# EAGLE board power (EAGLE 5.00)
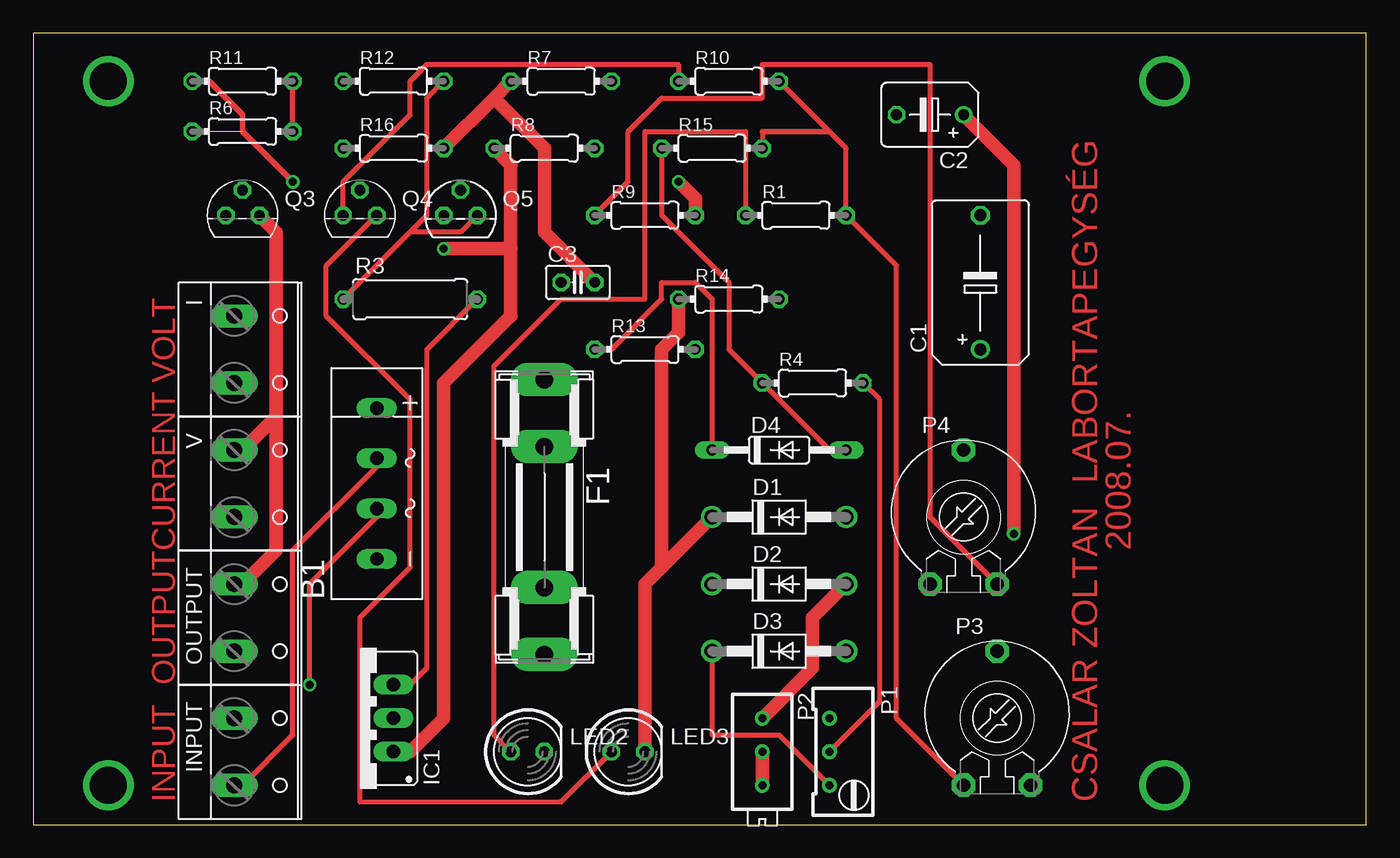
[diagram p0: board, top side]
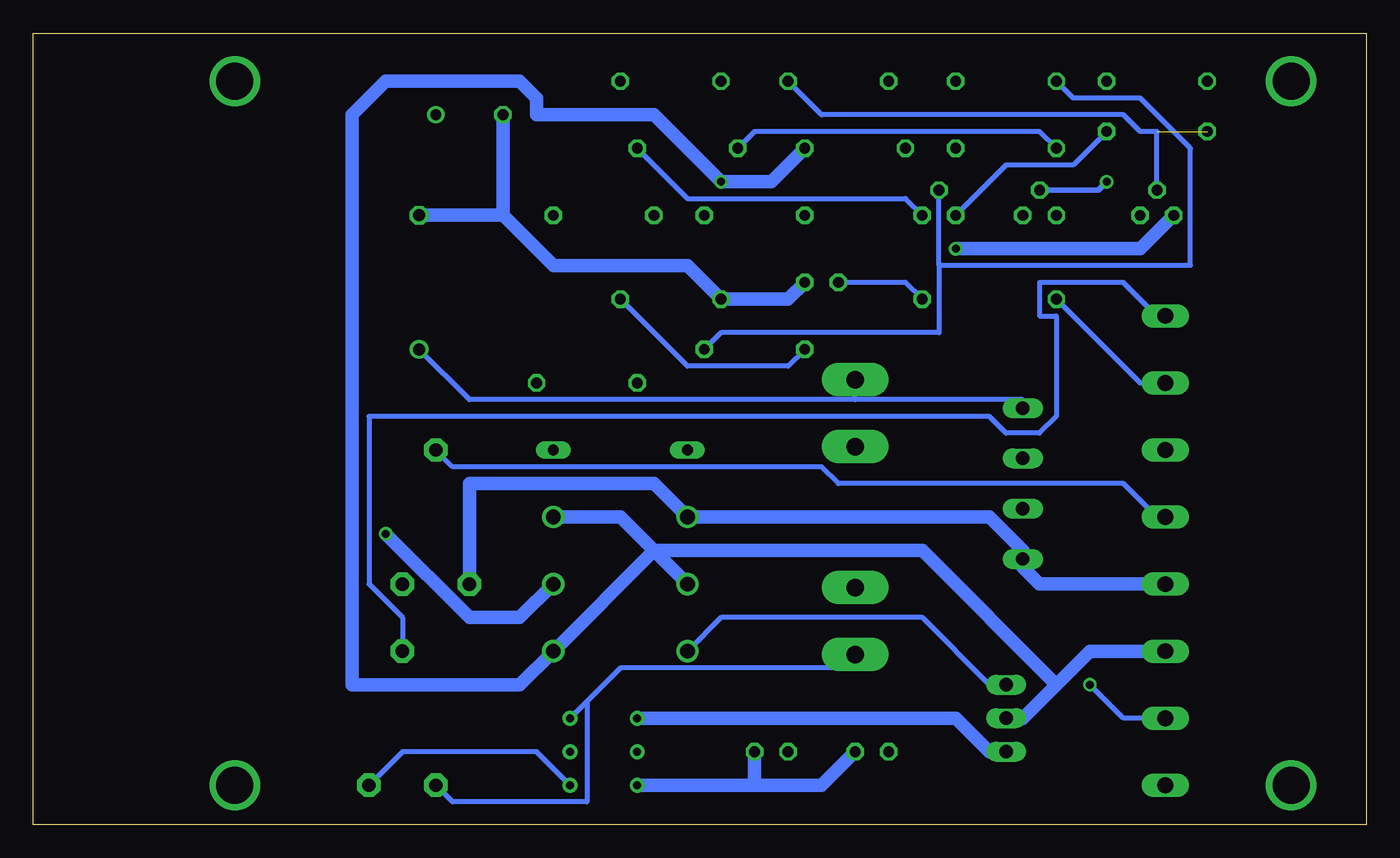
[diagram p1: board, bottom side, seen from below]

Size 101 x 60 mm. Coordinates in mm from the lower left corner, seen from the top.
Outline: 0,0 101,0 101,60 0,60 0,0
Copper layers (1*16): Top 0.035mm / dielectric 1.5mm / Bottom 0.035mm
Design rules "default": minimum track width 10mil, minimum drill 24mil, track to track 8mil, track to pad 8mil, pad to pad 8mil, via to via 8mil, smd to smd 8mil, copper to edge 40mil, drill to drill 8mil, minimum pad ring 10mil, minimum via ring 8mil, stop-mask expansion 4mil, vias tented up to drill 0mil, thermal gap 10mil
Net classes: 0 default: width 0.381 mm; 1 1: width 1.016 mm, drill 0.584 mm, clearance 0.381 mm

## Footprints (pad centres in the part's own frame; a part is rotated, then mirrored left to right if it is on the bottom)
2KBP = drill 1.016 long: + 5.715,0; - -5.715,0; AC1 -1.905,0; AC2 1.905,0
B45181C = drill 0.914 round: + -5.08,0 | drill 0.914 octagon: - 5.08,0
B45181B = drill 0.813 round: + -2.54,0 | drill 0.813 octagon: - 2.54,0
C025-025X050 = drill 0.813 octagon: 1 -1.27,0; 2 1.27,0
DO41-10 = drill 1.118 round: A 5.08,0; C -5.08,0
DO35-10 = drill 0.813 long: A 5.08,0; C -5.08,0
SHK20L = drill 1.321 pad 2.54 long: 1A -10.414,0; 1B -5.334,0; 2A 10.414,0; 2B 5.334,0
W237-132 = drill 1.194 long: 1 -2.54,-0.635; 2 2.54,-0.635
317TS = drill 1.016 long: 1 -2.54,-2.54; 2 0,-2.54; 3 2.54,-2.54
LED5MM = drill 0.813 octagon: A -1.27,0; K 1.27,0
RTRIM64W = drill 0.61 round: 1 1.27,-2.54; 2 1.27,0; 3 1.27,2.54
RTRIM3296X = drill 0.61 round: 1 0,-2.54; 2 0,0; 3 0,2.54
PT-10 = drill 1.016 pad 1.778 octagon: 1 -2.54,-5.08; 2 2.54,-5.08; 3 0,5.08
TO92 = drill 0.813 octagon: 1 1.27,0; 2 0,1.905; 3 -1.27,0
0204/7 = drill 0.813 octagon: 1 -3.81,0; 2 3.81,0
0309/10 = drill 0.813 octagon: 1 -5.08,0; 2 5.08,0

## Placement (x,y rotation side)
B1  [2KBP]  26.03,25.87 90 top
C1  2200  [B45181C]  71.75,41.11 90 top
C2  [B45181B]  67.94,53.81 180 top
C3  [C025-025X050]  41.27,41.11 0 top
D1  1N4004  [DO41-10]  56.51,23.33 0 top
D2  1N4004  [DO41-10]  56.51,18.25 0 top
D3  1N4004  [DO41-10]  56.51,13.17 0 top
D4  1N4148  [DO35-10]  56.51,28.41 0 top
F1  FUSESHK20L  [SHK20L]  38.73,23.33 270 top
I  [W237-132]  15.87,36.03 270 top
IC1  [317TS]  24.76,8.09 90 top
INPUT  [W237-132]  15.87,5.55 270 top
LED2  [LED5MM]  37.46,5.55 0 top
LED3  [LED5MM]  45.08,5.55 0 top
OUTPUT  [W237-132]  15.87,15.71 270 top
P1  [RTRIM64W]  61.59,5.55 180 top
P2  [RTRIM3296X]  55.24,5.55 180 top
P3  1  [PT-10]  73.02,8.09 0 top
P4  [PT-10]  70.48,23.33 0 top
Q3  BC237  [TO92]  15.87,46.19 0 top
Q4  BC237  [TO92]  24.76,46.19 0 top
Q5  BC327  [TO92]  32.38,46.19 0 top
R1  2.7  [0204/7]  57.78,46.19 0 top
R3  2.2  [0309/10]  28.57,39.84 0 top
R4  [0204/7]  59.05,33.49 0 top
R6  [0204/7]  15.87,52.54 0 top
R7  [0204/7]  40,56.35 0 top
R8  [0204/7]  38.73,51.27 0 top
R9  [0204/7]  46.35,46.19 0 top
R10  [0204/7]  52.7,56.35 0 top
R11  [0204/7]  15.87,56.35 0 top
R12  [0204/7]  27.3,56.35 0 top
R13  [0204/7]  46.35,36.03 0 top
R14  [0204/7]  52.7,39.84 0 top
R15  [0204/7]  51.43,51.27 0 top
R16  [0204/7]  27.3,51.27 0 top
V  [W237-132]  15.87,25.87 270 top

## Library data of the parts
B1 = rectifier
C1-C3 P1-P4 R1 R3 R4 R6-R16 = rcl
D1-D4 = diode
F1 = fuse
I INPUT OUTPUT V = con-wago-508
IC1 = v-reg
LED2 LED3 = led
Q3 Q4 = transistor-npn
Q5 = transistor-pnp

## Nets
INPUT: B1.AC2 INPUT.2
N$1: LED2.A R1.1
N$4: B1.+ C1.+ F1.1A
N$7: Q3.2 R6.1 R7.2
N$9: LED3.A Q4.1
N$10: C3.1 D3.C IC1.3 P1.3 P3.2 R3.2
N$11: P1.2 R4.2
N$12: Q4.3 R10.1
N$13: Q4.2 R11.1
N$14: Q5.3 R6.2 R11.2
N$15: P4.2 R9.1
N$16 [1]: C2.+ D2.A IC1.1 P2.1 Q3.3 R8.1
N$17: D4.C R13.1 R14.2
N$18: Q5.2 R12.1 R13.2
N$19 [1]: D1.A D2.C D3.A IC1.2 OUTPUT.2 R8.2 R9.2
N$20: I.1 P3.3
N$22: P4.3 V.2
N$23: F1.2A I.2 P1.1 P3.1 Q5.1 R1.2 R3.1 R10.2 R12.2 R15.2
N$24 [1]: B1.- C1.- C2.- C3.2 D1.C LED2.K LED3.K OUTPUT.1 P2.2 P2.3 P4.1 Q3.1 R7.1 R14.1 R16.2 V.1
N$25: D4.A R4.1 R15.1 R16.1
N$31: B1.AC1 INPUT.1

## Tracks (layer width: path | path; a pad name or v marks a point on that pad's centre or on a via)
INPUT
  Top 0.381: B1.AC2 26.03,27.14 19.68,20.79 19.68,6.82 15.87,3.01 INPUT.2
N$1
  Top 0.381: LED2.A 34.92,6.82 34.92,34.76 40,39.84 46.35,39.84 46.35,52.54 53.97,52.54 R1.1
N$2  (via drill 2.8 pad 3.81)
  other vias: 5.71,56.35
N$3  (via drill 2.8 pad 3.81)
  other vias: 5.71,3.01
N$4
  Bottom 0.381: C1.+ 67.94,32.22 38.73,32.22 | 38.73,32.22 26.03,32.22 B1.+ | 38.73,32.22 F1.1A
N$5  (via drill 2.8 pad 3.81)
  other vias: 85.72,3.01
N$6  (via drill 2.8 pad 3.81)
  other vias: 85.72,56.35
N$7  (1 unrouted)
  Bottom 0.381: R7.2 41.27,53.81 18.41,53.81 17.14,52.54 15.87,52.54 Q3.2
N$9
  Top 0.381: LED3.A 40,1.74 24.76,1.74 24.76,15.71 28.57,19.52 28.57,32.22 22.22,38.57 22.22,42.38 Q4.1
N$10
  Top 0.381: P1.3 56.51,6.82 51.43,6.82 D3.C | R3.2 29.84,36.03 29.84,11.9 28.57,10.63 IC1.3
  Bottom 0.381: R3.2 34.92,41.11 C3.1 | D3.C 48.89,15.71 33.65,15.71 28.57,10.63 IC1.3 | P3.2 73.02,5.55 62.86,5.55 P1.3
N$11
  Top 0.381: P1.2 64.13,9.36 64.13,32.22 R4.2
N$12
  Top 0.381: Q4.3 23.49,48.73 28.57,53.81 28.57,56.35 29.84,57.62 48.89,57.62 R10.1
N$13  (via drill 0.6)
  Top 0.406: R11.1 13.33,56.35 15.87,53.81 15.87,52.54 v19.68,48.73
  Bottom 0.406: Q4.2 20.32,48.09 v19.68,48.73
N$14
  Top 0.381: R6.2 R11.2
  Bottom 0.381: Q5.3 27.3,50 22.22,50 R6.2
N$15
  Top 0.381: R9.1 45.08,48.73 45.08,52.54 47.62,55.08 55.24,55.08 55.24,57.62 67.94,57.62 67.94,23.33 P4.2
N$16  (via drill 0.61)
  Top 1.016: 36.19,43.65 v31.11,43.65 | 36.19,43.65 36.19,50 R8.1 | P2.1 59.05,11.9 59.05,15.71 D2.A | C2.+ 74.29,50 v74.29,22.06 | 36.19,43.65 36.19,38.57 31.11,33.49 31.11,8.09 28.57,5.55 IC1.1
  Bottom 1.016: Q3.3 17.14,43.65 v31.11,43.65 | v74.29,22.06 67.94,15.71 64.13,15.71 D2.A | P2.1 31.11,8.09 28.57,5.55 IC1.1
N$17
  Top 0.381: D4.C 51.43,39.84 50.16,41.11 47.62,41.11 47.62,39.84 43.81,36.03 R13.1
  Bottom 0.381: R14.2 51.43,34.76 43.81,34.76 R13.1
N$18
  Bottom 0.381: 32.38,42.38 32.38,37.3 48.89,37.3 R13.2 | 32.38,42.38 Q5.2 | R12.1 22.22,55.08 17.14,55.08 13.33,51.27 13.33,42.38 32.38,42.38
N$19  (via drill 0.61)
  Top 1.016: v48.89,48.73 50.16,47.46 R9.2
  Bottom 1.016: 23.49,10.63 20.95,13.17 OUTPUT.2 | 23.49,10.63 26.03,8.09 IC1.2 | R8.2 45.08,48.73 v48.89,48.73 53.97,53.81 62.86,53.81 62.86,55.08 64.13,56.35 74.29,56.35 76.83,53.81 76.83,10.63 64.13,10.63 D3.A 53.97,20.79 | 53.97,20.79 56.51,23.33 D1.A | 53.97,20.79 D2.C | 23.49,10.63 33.65,20.79 53.97,20.79
N$20
  Bottom 0.381: P3.3 73.02,15.71 75.56,18.25 75.56,30.95 28.57,30.95 27.3,29.68 24.76,29.68 23.49,30.95 23.49,38.57 24.76,38.57 24.76,41.11 18.41,41.11 15.87,38.57 I.1
N$22
  Bottom 0.381: P4.3 69.21,27.14 41.27,27.14 40,25.87 18.41,25.87 15.87,23.33 V.2
N$23
  Top 0.381: R10.2 60.32,52.54 61.59,51.27 R1.2 65.4,42.38 65.4,8.09 P3.1 | 55.24,52.54 R15.2 | R12.2 29.84,55.08 29.84,46.19 28.57,44.92 | 28.57,44.92 R3.1 | Q5.1 32.38,44.92 28.57,44.92
  Top 0.406: 60.32,52.54 55.24,52.54
  Bottom 0.381: 59.05,9.36 56.51,11.9 40,11.9 F1.2A | 59.05,9.36 P1.1 | P3.1 69.21,1.74 59.05,1.74 59.05,9.36 | Q5.1 34.92,47.46 51.43,47.46 R15.2 | R3.1 17.14,33.49 I.2
N$24
  Top 1.016: 34.92,55.08 R7.1 | 34.92,55.08 R16.2 | C3.2 38.73,44.92 38.73,51.27 34.92,55.08 | Q3.1 18.41,44.92 18.41,30.95 | 18.41,30.95 15.87,28.41 V.1 | 18.41,30.95 18.41,20.79 15.87,18.25 OUTPUT.1 | P2.3 P2.2 | 47.62,19.52 46.35,18.25 LED3.K | D1.C 47.62,19.52 | R14.1 48.89,37.3 47.62,36.03 47.62,19.52
  Bottom 1.016: 65.4,46.19 C2.- | 65.4,46.19 C1.- | C3.2 43.81,39.84 R14.1 51.43,42.38 61.59,42.38 65.4,46.19 | OUTPUT.1 24.76,18.25 26.03,19.52 B1.- 26.03,20.79 28.57,23.33 D1.C 53.97,25.87 67.94,25.87 P4.1 | LED2.K 41.27,3.01 46.35,3.01 | 46.35,3.01 P2.3 | LED3.K 46.35,3.01
N$25
  Top 0.381: D4.A 60.32,28.41 R4.1 52.7,36.03 52.7,41.11 47.62,46.19 R15.1
  Bottom 0.381: R16.1 24.76,52.54 46.35,52.54 R15.1
N$31  (via drill 0.61)
  Top 0.381: v20.95,10.63 20.95,18.25 26.03,23.33 B1.AC1
  Bottom 0.381: v20.95,10.63 18.41,8.09 INPUT.1

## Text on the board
Top: VOLT | LABORTAPEGYSÉG | CURRENT | 2008.07. | OUTPUT | INPUT | CSALAR ZOLTAN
